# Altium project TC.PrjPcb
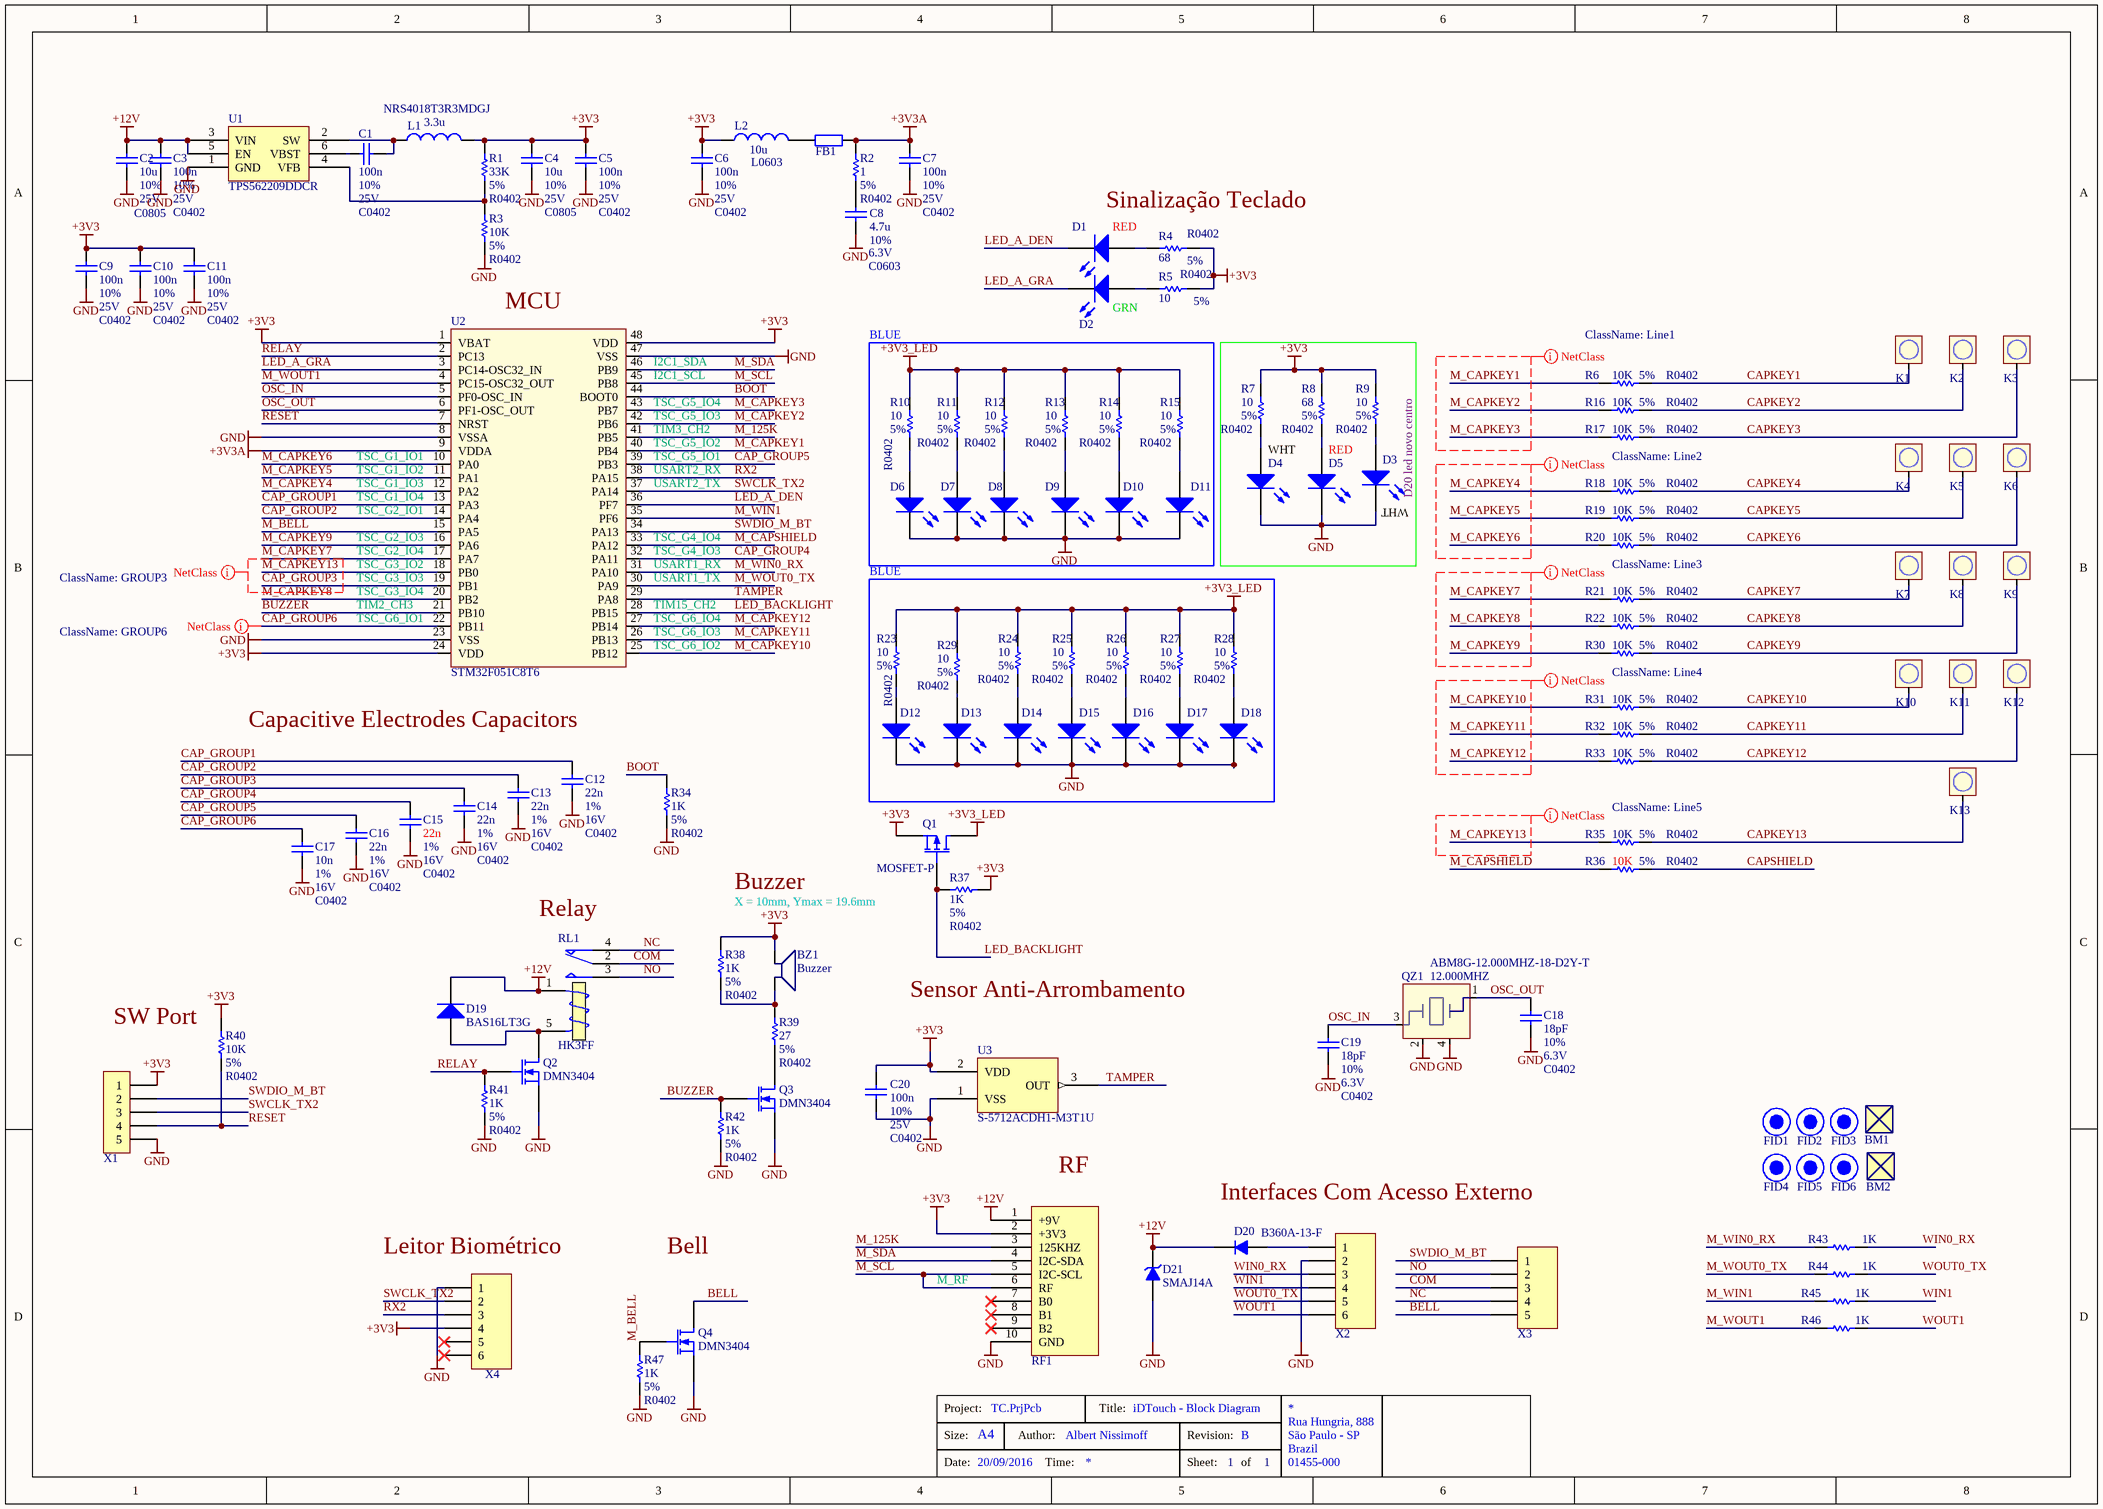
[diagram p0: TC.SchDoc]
ProjectRevision: A
1 sheet, 127 parts. Net scope: global (net labels, ports and power ports of the same name join across sheets).
Board files: TC Panel.PcbDoc, TC.PcbDoc

## Sheet TC.SchDoc: iDTouch - Block Diagram
size A3; Date: 20/09/2016; Author: Albert Nissimoff; Organization: Control iD; Address1: Rua Hungria, 888; Address2: São Paulo - SP; Address3: Brazil; Address4: 01455-000; DocumentNumber: 1; Revision: B; SheetNumber: 1; SheetTotal: 1

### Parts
BM1  BADMARK  [BADMARK]  (value not drawn)
BM2  BADMARK  [BADMARK]  (value not drawn)
BZ1  Buzzer  [Buzzer]
C1  value 100n  Tolerance: 10%  MAX VDC: 25V  [C0402]  (hidden comment: Cap0402)
C2  value 10u  Tolerance: 10%  MAX VDC: 25V  [C0805]  (hidden comment: Cap0805)
C3  value 100n  Tolerance: 10%  MAX VDC: 25V  [C0402]  (hidden comment: Cap0402)
C4  value 10u  Tolerance: 10%  MAX VDC: 25V  [C0805]  (hidden comment: Cap0805)
C5  value 100n  Tolerance: 10%  MAX VDC: 25V  [C0402]  (hidden comment: Cap0402)
C6  value 100n  Tolerance: 10%  MAX VDC: 25V  [C0402]  (hidden comment: Cap0402)
C7  value 100n  Tolerance: 10%  MAX VDC: 25V  [C0402]  (hidden comment: Cap0402)
C8  value 4.7u  Tolerance: 10%  MAX VDC: 6.3V  [C0603]  (hidden comment: Cap0603)
C9  value 100n  Tolerance: 10%  MAX VDC: 25V  [C0402]  (hidden comment: Cap0402)
C10  value 100n  Tolerance: 10%  MAX VDC: 25V  [C0402]  (hidden comment: Cap0402)
C11  value 100n  Tolerance: 10%  MAX VDC: 25V  [C0402]  (hidden comment: Cap0402)
C12  value 22n  Tolerance: 1%  MAX VDC: 16V  [C0402]  (hidden comment: Cap0402)
C13  value 22n  Tolerance: 1%  MAX VDC: 16V  [C0402]  (hidden comment: Cap0402)
C14  value 22n  Tolerance: 1%  MAX VDC: 16V  [C0402]  (hidden comment: Cap0402)
C15  value 22n  Tolerance: 1%  MAX VDC: 16V  [C0402]  (hidden comment: Cap0402)
C16  value 22n  Tolerance: 1%  MAX VDC: 16V  [C0402]  (hidden comment: Cap0402)
C17  value 10n  Tolerance: 1%  MAX VDC: 16V  [C0402]  (hidden comment: Cap0402)
C18  value 18pF  Tolerance: 10%  MAX VDC: 6.3V  [C0402]  (hidden comment: Cap0402)
C19  value 18pF  Tolerance: 10%  MAX VDC: 6.3V  [C0402]  (hidden comment: Cap0402)
C20  value 100n  Tolerance: 10%  MAX VDC: 25V  [C0402]  (hidden comment: Cap0402)
D1  XZMDK87W  [LTST-S270TBKT]  (value not drawn)
D2  XZDGK87W  [LTST-S270TBKT]  (value not drawn)
D3  XZCWD87F  [LTST-S270TBKT]  (value not drawn)
D4  XZCWD87F  [LTST-S270TBKT]  (value not drawn)
D5  XZMDK87W  [LTST-S270TBKT]  (value not drawn)
D6  XZCBD87W  [LTST-S270TBKT]  (value not drawn)
D7  XZCBD87W  [LTST-S270TBKT]  (value not drawn)
D8  XZCBD87W  [LTST-S270TBKT]  (value not drawn)
D9  XZCBD87W  [LTST-S270TBKT]  (value not drawn)
D10  XZCBD87W  [LTST-S270TBKT]  (value not drawn)
D11  XZCBD87W  [LTST-S270TBKT]  (value not drawn)
D12  XZCBD87W  [LTST-S270TBKT]  (value not drawn)
D13  XZCBD87W  [LTST-S270TBKT]  (value not drawn)
D14  XZCBD87W  [LTST-S270TBKT]  (value not drawn)
D15  XZCBD87W  [LTST-S270TBKT]  (value not drawn)
D16  XZCBD87W  [LTST-S270TBKT]  (value not drawn)
D17  XZCBD87W  [LTST-S270TBKT]  (value not drawn)
D18  XZCBD87W  [LTST-S270TBKT]  (value not drawn)
D19  BAS16LT3G  [BAS16LT3G]
D20  B360A-13-F  [SMA]
D21  SMAJ14A  [SMA]
FB1  Ferrite Bead  [FB0402]  (value not drawn)
FID1  FIDUCIAL  [FIDUCIAL-1p5X3]  (value not drawn)  (no BOM)
FID2  FIDUCIAL  [FIDUCIAL-1p5X3]  (value not drawn)  (no BOM)
FID3  FIDUCIAL  [FIDUCIAL-1p5X3]  (value not drawn)  (no BOM)
FID4  FIDUCIAL  [FIDUCIAL-1p5X3]  (value not drawn)  (no BOM)
FID5  FIDUCIAL  [FIDUCIAL-1p5X3]  (value not drawn)  (no BOM)
FID6  FIDUCIAL  [FIDUCIAL-1p5X3]  (value not drawn)  (no BOM)
K1  CAP_KEY  [CAPKEY - NEW]  (value not drawn)
K2  CAP_KEY  [CAPKEY - NEW]  (value not drawn)
K3  CAP_KEY  [CAPKEY - NEW]  (value not drawn)
K4  CAP_KEY  [CAPKEY - NEW]  (value not drawn)
K5  CAP_KEY  [CAPKEY - NEW]  (value not drawn)
K6  CAP_KEY  [CAPKEY - NEW]  (value not drawn)
K7  CAP_KEY  [CAPKEY - NEW]  (value not drawn)
K8  CAP_KEY  [CAPKEY - NEW]  (value not drawn)
K9  CAP_KEY  [CAPKEY - NEW]  (value not drawn)
K10  CAP_KEY  [CAPKEY - NEW]  (value not drawn)
K11  CAP_KEY  [CAPKEY - NEW]  (value not drawn)
K12  CAP_KEY  [CAPKEY - NEW]  (value not drawn)
K13  CAP_KEY  [CAPKEY - NEW]  (value not drawn)
L1  value 3.3u  [NRS4018T3R3MDGJ]  (hidden comment: Inductor)
L2  value 10u  [L0603]  (hidden comment: Inductor)
Q1  MOSFET-P  [SOT23-3]
Q2  DMN3404  [SOT23-3]
Q3  DMN3404  [SOT23-3]
Q4  DMN3404  [SOT23-3]
QZ1  ABM8G-12.000MHZ-18-D2Y-T  value 12.000MHZ  [ABM8G-12.000MHZ-18-D2Y-T]
R1  value 33K  Tolerance: 5%  [R0402]  (hidden comment: Res0402)
R2  value 1  Tolerance: 5%  [R0402]  (hidden comment: Res0402)
R3  value 10K  Tolerance: 5%  [R0402]  (hidden comment: Res0402)
R4  value 68  Tolerance: 5%  [R0402]  (hidden comment: Res0402)
R5  value 10  Tolerance: 5%  [R0402]  (hidden comment: Res0402)
R6  value 10K  Tolerance: 5%  [R0402]  (hidden comment: Res0402)
R7  value 10  Tolerance: 5%  [R0402]  (hidden comment: Res0402)
R8  value 68  Tolerance: 5%  [R0402]  (hidden comment: Res0402)
R9  value 10  Tolerance: 5%  [R0402]  (hidden comment: Res0402)
R10  value 10  Tolerance: 5%  [R0402]  (hidden comment: Res0402)
R11  value 10  Tolerance: 5%  [R0402]  (hidden comment: Res0402)
R12  value 10  Tolerance: 5%  [R0402]  (hidden comment: Res0402)
R13  value 10  Tolerance: 5%  [R0402]  (hidden comment: Res0402)
R14  value 10  Tolerance: 5%  [R0402]  (hidden comment: Res0402)
R15  value 10  Tolerance: 5%  [R0402]  (hidden comment: Res0402)
R16  value 10K  Tolerance: 5%  [R0402]  (hidden comment: Res0402)
R17  value 10K  Tolerance: 5%  [R0402]  (hidden comment: Res0402)
R18  value 10K  Tolerance: 5%  [R0402]  (hidden comment: Res0402)
R19  value 10K  Tolerance: 5%  [R0402]  (hidden comment: Res0402)
R20  value 10K  Tolerance: 5%  [R0402]  (hidden comment: Res0402)
R21  value 10K  Tolerance: 5%  [R0402]  (hidden comment: Res0402)
R22  value 10K  Tolerance: 5%  [R0402]  (hidden comment: Res0402)
R23  value 10  Tolerance: 5%  [R0402]  (hidden comment: Res0402)
R24  value 10  Tolerance: 5%  [R0402]  (hidden comment: Res0402)
R25  value 10  Tolerance: 5%  [R0402]  (hidden comment: Res0402)
R26  value 10  Tolerance: 5%  [R0402]  (hidden comment: Res0402)
R27  value 10  Tolerance: 5%  [R0402]  (hidden comment: Res0402)
R28  value 10  Tolerance: 5%  [R0402]  (hidden comment: Res0402)
R29  value 10  Tolerance: 5%  [R0402]  (hidden comment: Res0402)
R30  value 10K  Tolerance: 5%  [R0402]  (hidden comment: Res0402)
R31  value 10K  Tolerance: 5%  [R0402]  (hidden comment: Res0402)
R32  value 10K  Tolerance: 5%  [R0402]  (hidden comment: Res0402)
R33  value 10K  Tolerance: 5%  [R0402]  (hidden comment: Res0402)
R34  value 1K  Tolerance: 5%  [R0402]  (hidden comment: Res0402)
R35  value 10K  Tolerance: 5%  [R0402]  (hidden comment: Res0402)
R36  value 10K  Tolerance: 5%  [R0402]  (hidden comment: Res0402)
R37  value 1K  Tolerance: 5%  [R0402]  (hidden comment: Res0402)
R38  value 1K  Tolerance: 5%  [R0402]  (hidden comment: Res0402)
R39  value 27  Tolerance: 5%  [R0402]  (hidden comment: Res0402)
R40  value 10K  Tolerance: 5%  [R0402]  (hidden comment: Res0402)
R41  value 1K  Tolerance: 5%  [R0402]  (hidden comment: Res0402)
R42  value 1K  Tolerance: 5%  [R0402]  (hidden comment: Res0402)
R43  value 1K  [R0402]  (hidden comment: Res0402)
R44  value 1K  [R0402]  (hidden comment: Res0402)
R45  value 1K  [R0402]  (hidden comment: Res0402)
R46  value 1K  [R0402]  (hidden comment: Res0402)
R47  value 1K  Tolerance: 5%  [R0402]  (hidden comment: Res0402)
RF1  REPASK/REPMIF  [REPASK_REPMIF]  (value not drawn)
RL1  HK3FF  [HK3FF]
U1  TPS562209DDCR  [SOT6]
U2  STM32F051C8T6  [LQFP48]
U3  S-5712ACDH1-M3T1U  [SOT23-3]
X1  Header 5  [1X05]  (value not drawn)
X2  JST6_VERT  [JST6_VERT]  (value not drawn)
X3  JST5_VERT  [JST5_VERT]  (value not drawn)
X4  JST6_HORIZ  [JST6_HORIZ]  (value not drawn)

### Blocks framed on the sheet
BLUE: D6-D11 R10-R15
BLUE: D12-D18 R23-R29

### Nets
+3V3: BZ1.1 C4.1 C5.2 C6.2 C9.2 C10.2 C11.2 C20.2 L1.2 L2.1 Q1.3(S) R1.2 R4.1 R5.1 R7.2 R8.2 R9.2 R37.2 R38.2 R40.2 RF1.2(+3V3) U2.1(VBAT) U2.24(VDD) U2.48(VDD) U3.2(VDD) X1.1 X4.4
+3V3_LED: Q1.1(D) R10.2 R11.2 R12.2 R13.2 R14.2 R15.2 R23.2 R24.2 R25.2 R26.2 R27.2 R28.2 R29.2
+3V3A: C7.2 FB1.2 R2.2 U2.9(VDDA)
+12V: C2.2 C3.2 D19.3(K) D20.2(K) D21.2(K) RF1.1(+9V) RL1.1(T1) U1.3(VIN) U1.5(EN)
GND: C2.1 C3.1 C4.2 C5.1 C6.1 C7.1 C8.1 C9.1 C10.1 C11.1 C12.1 C13.1 C14.1 C15.1 C16.1 C17.1 C18.1 C19.1 C20.1 D3.2(K) D4.2(K) D5.2(K) D6.2(K) D7.2(K) D8.2(K) D9.2(K) D10.2(K) D11.2(K) D12.2(K) D13.2(K) D14.2(K) D15.2(K) D16.2(K) D17.2(K) D18.2(K) D21.1(A) Q2.3(S) Q3.3(S) Q4.3(S) QZ1.2 QZ1.4 R3.1 R34.2 R41.1 R42.2 R47.2 RF1.10(GND) U1.1(GND) U2.8(VSSA) U2.23(VSS) U2.47(VSS) U3.1(VSS) X1.5 X2.2 X4.1
BELL: Q4.1(D) X3.5
BOOT: R34.1 U2.44(BOOT0)
BUZZER: Q3.2(G) R42.1 U2.21(PB10)
CAP_GROUP1: C12.2 U2.13(PA3)
CAP_GROUP2: C13.2 U2.14(PA4)
CAP_GROUP3: C14.2 U2.19(PB1)
CAP_GROUP4: C15.2 U2.32(PA11)
CAP_GROUP5: C16.2 U2.39(PB3)
CAP_GROUP6: C17.2 U2.22(PB11)
CAPKEY1: K1.1 R6.2
CAPKEY2: K2.1 R16.2
CAPKEY3: K3.1 R17.2
CAPKEY4: K4.1 R18.2
CAPKEY5: K5.1 R19.2
CAPKEY6: K6.1 R20.2
CAPKEY7: K7.1 R21.2
CAPKEY8: K8.1 R22.2
CAPKEY9: K9.1 R30.2
CAPKEY10: K10.1 R31.2
CAPKEY11: K11.1 R32.2
CAPKEY12: K12.1 R33.2
CAPKEY13: K13.1 R35.2
CAPSHIELD: R36.2
COM: RL1.2(COM) X3.3
LED_A_DEN: D1.2(K) U2.36(PF7)
LED_A_GRA: D2.2(K) U2.3(PC14-OSC32_IN)
LED_BACKLIGHT: Q1.2(G) R37.1 U2.28(PB15)
M_125K: RF1.3(125KHZ) U2.41(PB5)
M_BELL: Q4.2(G) R47.1 U2.15(PA5)
M_CAPKEY1: R6.1 U2.40(PB4)
M_CAPKEY2: R16.1 U2.42(PB6)
M_CAPKEY3: R17.1 U2.43(PB7)
M_CAPKEY4: R18.1 U2.12(PA2)
M_CAPKEY5: R19.1 U2.11(PA1)
M_CAPKEY6: R20.1 U2.10(PA0)
M_CAPKEY7: R21.1 U2.17(PA7)
M_CAPKEY8: R22.1 U2.20(PB2)
M_CAPKEY9: R30.1 U2.16(PA6)
M_CAPKEY10: R31.1 U2.25(PB12)
M_CAPKEY11: R32.1 U2.26(PB13)
M_CAPKEY12: R33.1 U2.27(PB14)
M_CAPKEY13: R35.1 U2.18(PB0)
M_CAPSHIELD: R36.1 U2.33(PA12)
M_SCL: RF1.5(I2C-SCL) RF1.6(RF) U2.45(PB8)
M_SDA: RF1.4(I2C-SDA) U2.46(PB9)
M_WIN0_RX: R43.1 U2.31(PA10)
M_WIN1: R45.1 U2.35(PF6)
M_WOUT0_TX: R44.1 U2.30(PA9)
M_WOUT1: R46.1 U2.4(PC15-OSC32_OUT)
NC: RL1.4(NC) X3.4
NO: RL1.3(NO) X3.2
OSC_IN: C19.2 QZ1.3 U2.5(PF0-OSC_IN)
OSC_OUT: C18.2 QZ1.1 U2.6(PF1-OSC_OUT)
RELAY: Q2.2(G) R41.2 U2.2(PC13)
RESET: R40.1 U2.7(NRST) X1.4
RX2: U2.38(PA15) X4.3
SWCLK_TX2: U2.37(PA14) X1.3 X4.2
SWDIO_M_BT: U2.34(PA13) X1.2 X3.1
TAMPER: U2.29(PA8) U3.3(OUT)
WIN0_RX: R43.2 X2.3
WIN1: R45.2 X2.4
WOUT0_TX: R44.2 X2.5
WOUT1: R46.2 X2.6
NetBZ1_2: BZ1.2 R38.1 R39.2
NetC1_1: C1.1 L1.1 U1.2(SW)
NetC1_2: C1.2 U1.6(VBST)
NetC8_2: C8.2 R2.1
NetD1_1: D1.1(A) R4.2
NetD2_1: D2.1(A) R5.2
NetD3_1: D3.1(A) R9.1
NetD4_1: D4.1(A) R7.1
NetD5_1: D5.1(A) R8.1
NetD6_1: D6.1(A) R10.1
NetD7_1: D7.1(A) R11.1
NetD8_1: D8.1(A) R12.1
NetD9_1: D9.1(A) R13.1
NetD10_1: D10.1(A) R14.1
NetD11_1: D11.1(A) R15.1
NetD12_1: D12.1(A) R23.1
NetD13_1: D13.1(A) R29.1
NetD14_1: D14.1(A) R24.1
NetD15_1: D15.1(A) R25.1
NetD16_1: D16.1(A) R26.1
NetD17_1: D17.1(A) R27.1
NetD18_1: D18.1(A) R28.1
NetD19_1: D19.1(A) Q2.1(D) RL1.5(T2)
NetD20_1: D20.1(A) X2.1
NetFB1_1: FB1.1 L2.2
NetQ3_1: Q3.1(D) R39.1
NetR1_1: R1.1 R3.2 U1.4(VFB)

Not connected (* = marked no-connect by the designer): RF1 7(B0)* 8(B1)* 9(B2)*; X4 5* 6*

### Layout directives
net class Line1: M_CAPKEY1, M_CAPKEY2, M_CAPKEY3
net class Line2: M_CAPKEY4, M_CAPKEY5, M_CAPKEY6
net class Line3: M_CAPKEY7, M_CAPKEY8, M_CAPKEY9
net class Line4: M_CAPKEY10, M_CAPKEY11, M_CAPKEY12
net class Line5: M_CAPKEY13
net class GROUP3: CAP_GROUP3, M_CAPKEY7, M_CAPKEY13
net class GROUP6: CAP_GROUP6

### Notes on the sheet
- Sinalização Teclado
- (near D1) RED
- (near U2) MCU
- (near D2) GRN
- (near U2) I2C1_SCL
- (near U2) I2C1_SDA
- (near U2) TIM3_CH2
- (near U2) TSC_G5_IO4
- (near U2) TSC_G5_IO2
- (near U2) TSC_G5_IO3
- WHT
- RED
- (near U2) TSC_G1_IO1
- (near U2) TSC_G1_IO2
- (near U2) TSC_G1_IO3
- (near U2) TSC_G1_IO4
- (near U2) TSC_G2_IO1
- (near U2) USART2_TX
- (near U2) USART2_RX
- (near U2) TSC_G5_IO1
- (near D3) WHT
- D20 led novo centro
- (near U2) TSC_G2_IO3
- (near U2) TSC_G2_IO4
- (near U2) TSC_G3_IO2
- (near U2) TSC_G3_IO3
- (near U2) USART1_TX
- (near U2) USART1_RX
- (near U2) TSC_G4_IO4
- (near U2) TSC_G4_IO3
- (near U2) TSC_G6_IO1
- (near U2) TIM2_CH3
- (near U2) TSC_G3_IO4
- (near U2) TSC_G6_IO2
- (near U2) TSC_G6_IO3
- (near U2) TSC_G6_IO4
- (near U2) TIM15_CH2
- Capacitive Electrodes Capacitors
- (near RL1) Relay
- Buzzer
- X = 10mm, Ymax = 19.6mm
- (near R40) SW Port
- Sensor Anti-Arrombamento
- RF
- (near X4) Leitor Biométrico
- Bell
- Interfaces Com Acesso Externo
- M_RF

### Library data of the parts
BM1 BM2 = BADMARK: Bad Mark Indicator
BZ1 = Buzzer: Standard PTH Buzzer
C1 C3 C5-C7 C9-C20 = Cap0402: Capacitor
C2 C4 = Cap0805: Capacitor
C8 = Cap0603: Capacitor
D1-D18 = LTST-S270TBKT: Light-Emitting Diode (side-emitting)
D19 = BAS16LT3G: DIODE GEN PURP 75V 200MA SOT23-3; Manufacturer: ON Semiconductor; Diode Type: Standard; Current - Average Rectified (Io): 200mA (DC); Voltage - Forward (Vf) (Max) @ If: 1.25V @ 150mA; Speed: Small Signal =< 200mA (Io), Any Speed; Reverse Recovery Time (trr): 6ns; Current - Reverse Leakage @ Vr: 1µA @ 75V; Capacitance @ Vr, F: 2pF @ 0V, 1MHz
D20 = B360A: B360A Diode; Manufacturer: Diodes Incorporated; Diode Type: Schottky; Voltage - DC Reverse (Vr) (Max): 60V; Current - Average Rectified (Io): 3A; Voltage - Forward (Vf) (Max) @ If: 700mV @ 3A; Speed: Fast Recovery =< 500ns, > 200mA (Io); Current - Reverse Leakage @ Vr: 500µA @ 60V; Capacitance @ Vr, F: 200pF @ 4V, 1MHz
D21 = SMAJ14A: TVS DIODE 14VWM 23.2VC SMA; Manufacturer: Littelfuse Inc.; Type: Zener; Unidirectional Channels: 1; Voltage - Reverse Standoff (Typ): 14V; Voltage - Breakdown (Min): 15.6V; Voltage - Clamping (Max) @ Ipp: 23.2V; Current - Peak Pulse (10/1000µs): 17.2A; Power - Peak Pulse: 400W; Power Line Protection: No
FID1-FID6 = FIDUCIAL: Standard fiducial for Control iD boards; PCB Info: DNP
Q1 = MOSFET-P: P-Channel MOSFET
Q2-Q4 = DMN3404: DMN3404 N-Channel MOSFET
R1-R42 R47 = Res0402: Resistor
R43-R46 = Res0402: Resistor; Tolerance: 5%
RF1 = REPASK/REPMIF: Control iD RF Module
RL1 = HK3FF: SPDT Relay HK3FF
U3 = S-5712ACDH1-M3T1U: Hall effect sensor from Seiko
X1 = Header 5: Header, 5-Pin, Single row, 0.1"
X2 = JST6_VERT: Header, 6-Pin
X3 = JST5_VERT: Header, 5-Pin
X4 = JST6_HORIZ: Header, 6-Pin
